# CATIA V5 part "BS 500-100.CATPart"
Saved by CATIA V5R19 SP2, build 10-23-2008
Part number: BS 500-100
Bounding box of the stored display mesh (mm): x -18.951 to 18.951, y -18.952 to 18.952, z 0 to 230
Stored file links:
  C:\Users\Bora\Desktop\3D Katı model\BS serisi\BS 500\BS 500-100.CATPart
  C:\Program Files\Dassault Systemes\B19\intel_a\reffiles\standard\MetricThickPitch.txt
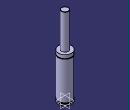
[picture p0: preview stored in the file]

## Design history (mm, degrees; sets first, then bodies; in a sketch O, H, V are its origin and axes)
Body1 (main body)
  Sketch1 on yz-plane, origin (0, 0, 0), H (0, 1, 0), V (0, 0, 1)
    point P1 (10, 229)
    point P3 (10, 229)
    point P5 (19, 119.5)
    point P6 (19, 117.5)
    point P9 (19, 119.5)
    point P14 (19, 117.5)
    line L1 (10, 229) -> (10, 129)
    arc A1 centre (9, 229) radius 1 from (10, 229) to (9, 230) ccw
    arc A2 centre (19, 118.5) radius 1 from (19, 119.5) to (19, 117.5) ccw
    line L2 (19, 0) -> (19, 4)
    line L3 (19, 119.5) -> (19, 129)
    line L4 (17, 7.5) -> (17, 4)
    line L5 (19, 7.5) -> (19, 117.5)
    line L6 (9, 230) -> (0, 230)
    point P15 (0, 230)
    line L7 (10, 129) -> (19, 129)
    line L8 (0, 0) -> (19, 0)
    line L9 (17, 7.5) -> (19, 7.5)
    line L10 (17, 4) -> (19, 4)
    coincidence: P15 V, P1 P3, P5 P9, P6 P14
    tangency: L6 A1
    horizontal: L7 H, L8 H, L9 H, L10 H
  Shaft1: profile Sketch1, axis Sketch1.V, angle 360
  Sketch2 on face of Shaft1 from Sketch1.L8, origin (0, 0, 0), H (1, 0, 0), V (0, -1, 0)
    point P1 (0, 0)
  Hole1: placed by Sketch2, at (0, 0, 0) direction (0, 0, 1), diameter 6.647, depth 4, threaded "M8", thread diameter 8, thread depth 4, pitch 1.25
